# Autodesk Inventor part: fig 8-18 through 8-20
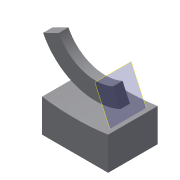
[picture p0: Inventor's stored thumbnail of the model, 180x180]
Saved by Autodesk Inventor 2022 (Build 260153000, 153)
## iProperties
Created: 2010-03
Part Number: fig 8-18 through 8-20
Document SubType Name: Modeling
Designer: CADSoft
Density: 1 g/cm^3
Material: Generic
Appearance: Default
Author: CADSoft
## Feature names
1. Extrusion1
2. Sweep3
## Parameters: d10 = 0, d13 = 0, d14 = 0
